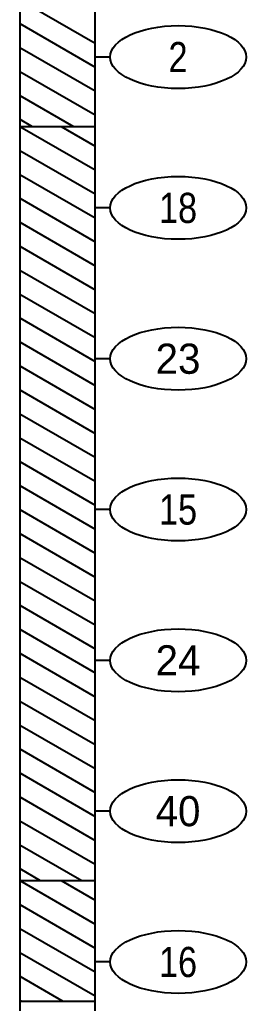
# Model space of a CAD drawing. Extents: x -76 to 974, y -1080 to -735.
# Drawn here: x -39.67 to -32.15, y -816.88 to -784.27 of the extents above; entities that cross this region are included whole.
import ezdxf
from ezdxf.enums import TextEntityAlignment as Align

# ---------------------------------------------------------------- set-up
doc = ezdxf.new("R2010")
doc.units = 0
doc.header["$LTSCALE"] = 0.36
doc.layers.add('27', color=7, linetype='Continuous', lineweight=40)

msp = doc.modelspace()

# ---------------------------------------------------------------- linework, layer by layer
at = {"layer": '27'}
for p, q in [((-39.6667, -782.8053), (-39.6667, -787.8053)), ((-37.1667, -787.8053), (-37.1667, -782.8053)), ((-39.6667, -783.599), (-37.1667, -785.0424)), ((-39.6667, -783.599), (-37.1667, -785.0424)), ((-39.6667, -784.3928), (-37.1667, -785.8362)), ((-39.6667, -785.1865), (-37.1667, -786.6299)), ((-39.6667, -785.1865), (-37.1667, -786.6299)), ((-36.6667, -785.5053), (-37.1667, -785.5053)), ((-39.6667, -785.9803), (-37.1667, -787.4237)), ((-39.6667, -786.774), (-37.8806, -787.8053)), ((-39.6667, -786.774), (-37.8806, -787.8053)), ((-39.6667, -787.5678), (-39.2554, -787.8053)), ((-39.6667, -787.8053), (-37.1667, -787.8053)), ((-39.6667, -787.8053), (-37.1667, -789.2487)), ((-39.6667, -787.8053), (-39.6667, -812.8053)), ((-38.2919, -787.8053), (-37.1667, -788.4549)), ((-38.2919, -787.8053), (-37.1667, -788.4549)), ((-37.1667, -812.8053), (-37.1667, -787.8053)), ((-39.6667, -788.599), (-37.1667, -790.0424)), ((-39.6667, -788.599), (-37.1667, -790.0424)), ((-39.6667, -789.3928), (-37.1667, -790.8362)), ((-39.6667, -790.1865), (-37.1667, -791.6299)), ((-39.6667, -790.1865), (-37.1667, -791.6299)), ((-36.6667, -790.5053), (-37.1667, -790.5053)), ((-39.6667, -790.9803), (-37.1667, -792.4237)), ((-39.6667, -791.774), (-37.1667, -793.2174)), ((-39.6667, -791.774), (-37.1667, -793.2174)), ((-39.6667, -792.5678), (-37.1667, -794.0112)), ((-39.6667, -793.3615), (-37.1667, -794.8049)), ((-39.6667, -793.3615), (-37.1667, -794.8049)), ((-39.6667, -794.1553), (-37.1667, -795.5987)), ((-39.6667, -794.949), (-37.1667, -796.3924)), ((-39.6667, -794.949), (-37.1667, -796.3924)), ((-36.6667, -795.5053), (-37.1667, -795.5053)), ((-39.6667, -795.7428), (-37.1667, -797.1862)), ((-39.6667, -796.5365), (-37.1667, -797.9799)), ((-39.6667, -796.5365), (-37.1667, -797.9799)), ((-39.6667, -797.3303), (-37.1667, -798.7737)), ((-39.6667, -798.124), (-37.1667, -799.5674)), ((-39.6667, -798.124), (-37.1667, -799.5674)), ((-39.6667, -798.9178), (-37.1667, -800.3612)), ((-39.6667, -799.7115), (-37.1667, -801.1549)), ((-39.6667, -799.7115), (-37.1667, -801.1549)), ((-39.6667, -800.5053), (-37.1667, -801.9487)), ((-36.6667, -800.5053), (-37.1667, -800.5053)), ((-39.6667, -801.299), (-37.1667, -802.7424)), ((-39.6667, -801.299), (-37.1667, -802.7424)), ((-39.6667, -802.0928), (-37.1667, -803.5362)), ((-39.6667, -802.8865), (-37.1667, -804.3299)), ((-39.6667, -802.8865), (-37.1667, -804.3299)), ((-39.6667, -803.6803), (-37.1667, -805.1237)), ((-39.6667, -804.474), (-37.1667, -805.9174)), ((-39.6667, -804.474), (-37.1667, -805.9174)), ((-39.6667, -805.2678), (-37.1667, -806.7112)), ((-36.6667, -805.5053), (-37.1667, -805.5053)), ((-39.6667, -806.0615), (-37.1667, -807.5049)), ((-39.6667, -806.0615), (-37.1667, -807.5049)), ((-39.6667, -806.8553), (-37.1667, -808.2987)), ((-39.6667, -807.649), (-37.1667, -809.0924)), ((-39.6667, -807.649), (-37.1667, -809.0924)), ((-39.6667, -808.4428), (-37.1667, -809.8862)), ((-39.6667, -809.2365), (-37.1667, -810.6799)), ((-39.6667, -809.2365), (-37.1667, -810.6799)), ((-39.6667, -810.0303), (-37.1667, -811.4737)), ((-36.6667, -810.5053), (-37.1667, -810.5053)), ((-39.6667, -810.824), (-37.1667, -812.2674)), ((-39.6667, -810.824), (-37.1667, -812.2674)), ((-39.6667, -811.6178), (-37.61, -812.8053)), ((-39.6667, -812.4115), (-38.9847, -812.8053)), ((-39.6667, -812.4115), (-38.9847, -812.8053)), ((-39.6667, -812.8053), (-37.1667, -812.8053)), ((-39.6667, -812.8053), (-37.1667, -814.2487)), ((-39.6667, -812.8053), (-39.6667, -816.8053)), ((-38.2919, -812.8053), (-37.1667, -813.4549)), ((-38.2919, -812.8053), (-37.1667, -813.4549)), ((-37.1667, -816.8053), (-37.1667, -812.8053)), ((-39.6667, -813.599), (-37.1667, -815.0424)), ((-39.6667, -813.599), (-37.1667, -815.0424)), ((-39.6667, -814.3928), (-37.1667, -815.8362)), ((-39.6667, -815.1865), (-37.1667, -816.6299)), ((-39.6667, -815.1865), (-37.1667, -816.6299)), ((-36.6667, -815.5053), (-37.1667, -815.5053)), ((-39.6667, -815.9803), (-38.2378, -816.8053)), ((-39.6667, -816.774), (-39.6126, -816.8053)), ((-39.6667, -816.774), (-39.6126, -816.8053)), ((-39.6667, -816.8053), (-37.1667, -816.8053)), ((-39.6667, -816.8053), (-39.6667, -826.0053)), ((-37.1667, -826.0053), (-37.1667, -816.8053))]:
    msp.add_line(p, q, dxfattribs=at)
for centre in [(-34.4093, -785.5053), (-34.4093, -790.5053), (-34.4094, -795.5053), (-34.4093, -800.5053), (-34.4093, -805.5053), (-34.4093, -810.5053), (-34.4093, -815.5053)]:
    msp.add_ellipse(centre, major_axis=(2.2574, 0), ratio=0.461538, dxfattribs=at)

# ---------------------------------------------------------------- texts
at = {"layer": '27', "width": 0.85}
for s, p in [('2', (-34.4166, -786.0053)), ('18', (-34.4167, -791.0053)), ('15', (-34.4167, -801.0053)), ('16', (-34.4166, -816.0053))]:
    msp.add_text(s, height=1, dxfattribs=at).set_placement(p, align=Align.CENTER)
at = {"layer": '27'}
for s, p in [('23', (-34.4167, -796.0053)), ('24', (-34.4167, -806.0053)), ('40', (-34.4167, -811.0053))]:
    msp.add_text(s, height=1, dxfattribs=at).set_placement(p, align=Align.CENTER)

doc.saveas('drawing.dxf')
